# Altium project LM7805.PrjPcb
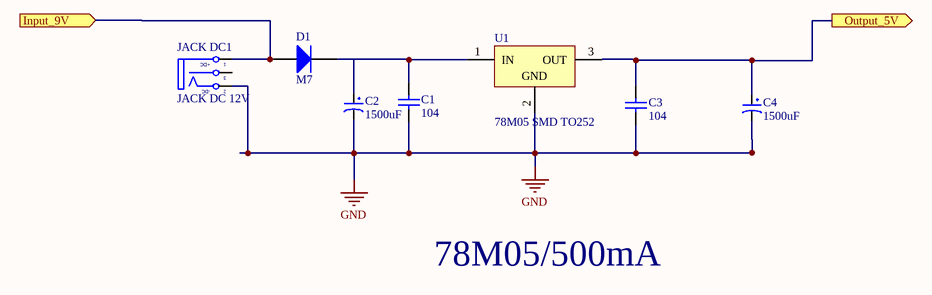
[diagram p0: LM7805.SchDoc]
1 sheet, 7 parts. Net scope: flat (ports and power ports of the same name join across sheets).
Board file: PCB1.PcbDoc

## Sheet LM7805.SchDoc
size A; SheetNumber: 1; SheetTotal: 1

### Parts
C1  104  [tu 1206]
C2  1500uF  [tu hoa 10mm]
C3  104  [tu 1206]
C4  1500uF  [tu hoa 10mm]
D1  M7  [DIODE SMA]
JACK_DC1  JACK DC 12V  [JACK DC 5.5]
U1  78M05 SMD TO252  [TO252]

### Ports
Input_9V (in), Output_5V (out)

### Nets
GND: C1.1 C2.2 C3.1 C4.2 JACK_DC1.2(TN) U1.2(GND)
NetC1_2: C1.2 C2.1 D1.2(K) U1.1(IN)
NetC3_2: C3.2 C4.1 U1.3(OUT) ; port Output_5V
NetD1_1: D1.1(A) JACK_DC1.1(T) ; port Input_9V

Not connected (* = marked no-connect by the designer): JACK_DC1 3(S)

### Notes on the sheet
- 78M05/500mA

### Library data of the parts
C1 C3 = Tu 1206 104 50V 20%: Dán; Don_Vi: Con; So_Chan: 2; Ten_Linh_Kien: Tụ 1206 104-0.1uF 20% 50V; Ma_Hang: MH004544
C2 C4 = Tu Hoa 1500uF 16V 10x20: Cắm; Don_Vi: Con; So_Chan: 2; Ten_Linh_Kien: Tụ Hóa 1500uF 16V 10x20MM; Ma_Hang: MH006603
D1 = Diode M7 ( 4007 ): Dán; Don_Vi: Con; Ten_Linh_Kien: Diode M7 1N4007 SMD 1A 1000V; Ma_Hang: MH000944
JACK_DC1 = JACK DC 5.5: Value: Jac DC
U1 = 78M05 SMD TO252: Dán; Don_Vi: Con; Ten_Linh_Kien: 78M05 TO252; Ma_Hang: MH001917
